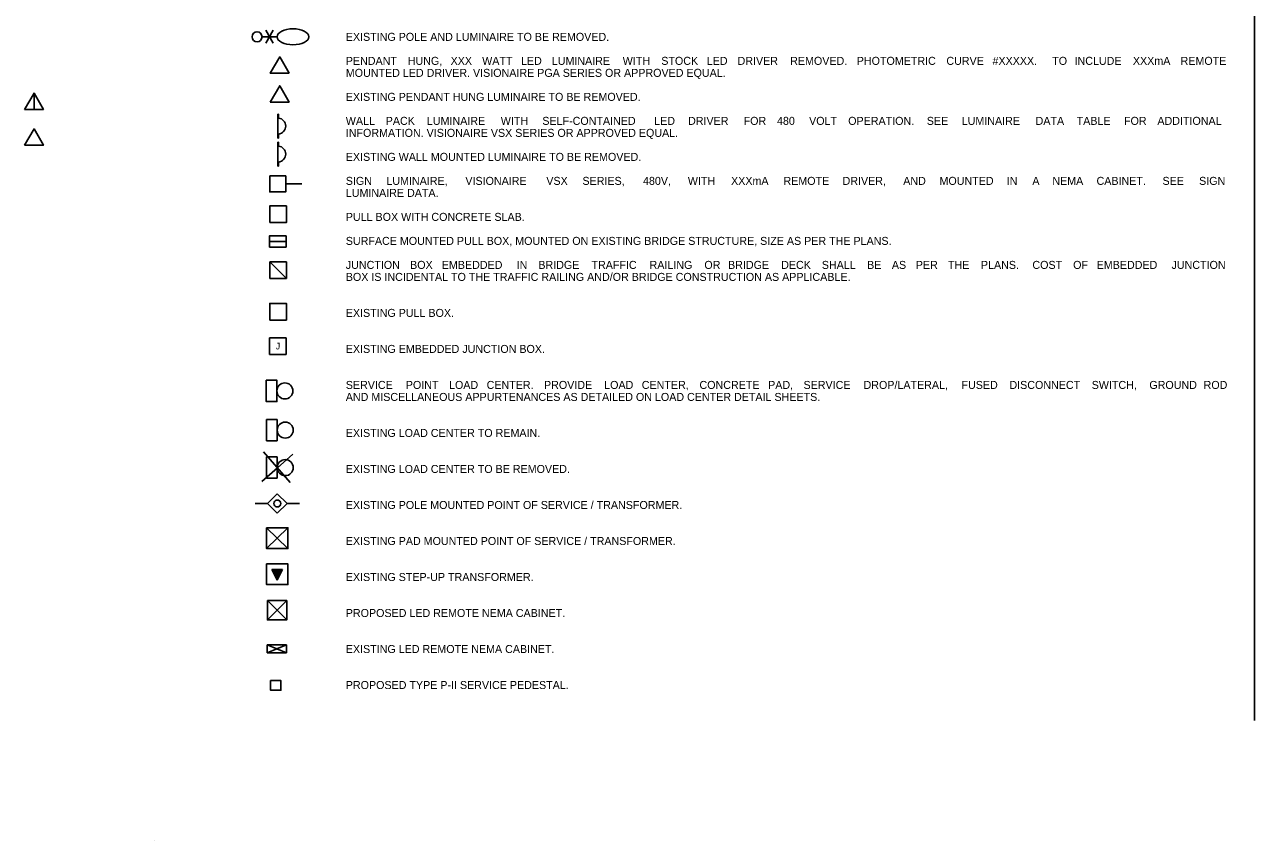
# Model space of a CAD drawing. Extents: x -1500 to -654, y -278 to 331.
# Drawn here: x -1500.3 to -1039.2, y -278.3 to 27.5 of the extents above; entities that cross this region are included whole.
import ezdxf

# ---------------------------------------------------------------- set-up
doc = ezdxf.new("R2010")
doc.units = 0
for name, color, linetype in [('AdhocPoint_dp', 7, 'Continuous'), ('ControllerP', 7, 'Continuous'), ('Default', 7, 'Continuous'), ('ElecMisc_ep', 7, 'Continuous'), ('JunctBoxA', 7, 'Continuous'), ('LoadCenter', 7, 'Continuous'), ('Logo_dp', 7, 'Continuous'), ('Miscellaneous3', 7, 'Continuous'), ('SheetBorder_dp', 7, 'Continuous'), ('SheetLines_dp', 7, 'Continuous'), ('SignPanel', 7, 'Continuous')]:
    doc.layers.add(name, color=color, linetype=linetype)

# ---------------------------------------------------------------- blocks, each defined once
blk = doc.blocks.new('EPoleLumRmv')
at = {"layer": 'Logo_dp'}
for p, q in [((-0.00352, -0.0088), (0.00352, -0.00474)), ((0.00352, -0.0088), (-0.00352, -0.00474)), ((0, -0.00271), (0, -0.01083))]:
    blk.add_line(p, q, dxfattribs=at)
blk.add_circle((0, 0), 0.00271, dxfattribs=at)
blk.add_ellipse((0, -0.01949), major_axis=(0, -0.00866), ratio=0.5, dxfattribs=at)

msp = doc.modelspace()

# ---------------------------------------------------------------- linework, layer by layer
at = {"layer": 'AdhocPoint_dp'}
for p, q in [((-1405.09, -6.02), (-1405.39, -6.02)), ((-1405.39, -6.02), (-1405.39, -15.02)), ((-1405.09, -7.54), (-1405.09, -6.02)), ((-1405.09, -15.02), (-1405.09, -13.51)), ((-1405.39, -15.02), (-1405.09, -15.02)), ((-1405.39, -25.52), (-1405.39, -16.52)), ((-1405.39, -16.52), (-1405.09, -16.52)), ((-1405.09, -16.52), (-1405.09, -18.04)), ((-1405.09, -25.52), (-1405.39, -25.52)), ((-1405.09, -24.01), (-1405.09, -25.52))]:
    msp.add_line(p, q, dxfattribs=at)
for points in [[(-1401.1, 9.31), (-1408.17, 9.31), (-1404.64, 15.43)], [(-1500.3, -4.28), (-1493.23, -4.28), (-1496.76, 1.84)], [(-1496.76, 1.84), (-1493.23, -4.28), (-1496.76, -4.28)], [(-1408.17, -1.53), (-1401.1, -1.53), (-1404.64, 4.59)], [(-1500.3, -17.69), (-1493.23, -17.69), (-1496.76, -11.57)]]:
    msp.add_lwpolyline(points, close=True, dxfattribs=at)
for centre in [(-1405.39, -10.52), (-1405.39, -21.02)]:
    msp.add_arc(centre, 3, 275.7392, 84.2608, dxfattribs=at)
at = {"layer": 'ControllerP'}
for p, q in [((-1409.27, -188.4), (-1401.98, -195.64)), ((-1409.27, -195.64), (-1401.98, -188.4)), ((-1409.3, -205.02), (-1402.08, -208.03)), ((-1402.08, -205.02), (-1409.3, -208.03)), ((-1409.3, -205.02), (-1402.08, -205.02)), ((-1409.3, -208.03), (-1409.3, -205.02)), ((-1402.08, -205.02), (-1402.08, -208.03)), ((-1402.08, -208.03), (-1409.3, -208.03))]:
    msp.add_line(p, q, dxfattribs=at)
for points in [[(-1409.27, -188.4), (-1401.98, -188.4), (-1401.98, -195.64), (-1409.27, -195.64)], [(-1408.08, -218.44), (-1404.18, -218.44), (-1404.18, -222.02), (-1408.08, -222.02)]]:
    msp.add_lwpolyline(points, close=True, dxfattribs=at)
at = {"layer": 'Default'}
msp.add_circle((-1405.56, -152.03), 1.3, dxfattribs=at)
at = {"layer": 'ElecMisc_ep'}
for p, q in [((-1409.57, -168.9), (-1401.56, -161.14)), ((-1409.57, -161.14), (-1401.56, -168.91)), ((-1405.56, -180.82), (-1407.56, -176.82)), ((-1407.56, -176.82), (-1403.56, -176.82)), ((-1407.36, -176.82), (-1405.56, -180.82)), ((-1405.56, -180.82), (-1407.16, -176.82)), ((-1405.56, -180.82), (-1406.96, -176.82)), ((-1405.56, -180.82), (-1406.76, -176.82)), ((-1405.56, -180.82), (-1406.56, -176.82)), ((-1405.56, -180.82), (-1406.36, -176.82)), ((-1405.56, -180.82), (-1406.16, -176.82)), ((-1405.56, -180.82), (-1405.96, -176.82)), ((-1405.56, -180.82), (-1405.76, -176.82)), ((-1405.56, -180.82), (-1405.36, -176.82)), ((-1405.56, -180.82), (-1405.16, -176.82)), ((-1405.56, -180.82), (-1404.96, -176.82)), ((-1405.56, -180.82), (-1404.76, -176.82)), ((-1405.56, -180.82), (-1404.36, -176.82)), ((-1405.56, -180.82), (-1404.16, -176.82)), ((-1405.56, -180.82), (-1403.96, -176.82)), ((-1405.56, -180.82), (-1403.77, -176.82)), ((-1403.56, -176.82), (-1405.56, -180.82)), ((-1405.56, -180.82), (-1405.56, -176.82)), ((-1405.56, -180.82), (-1404.56, -176.82))]:
    msp.add_line(p, q, dxfattribs=at)
for points in [[(-1409.57, -161.14), (-1401.56, -161.14), (-1401.56, -168.91), (-1409.57, -168.9)], [(-1409.57, -174.64), (-1401.56, -174.64), (-1401.56, -182.41), (-1409.57, -182.4)]]:
    msp.add_lwpolyline(points, close=True, dxfattribs=at)
at = {"layer": 'JunctBoxA'}
for p, q in [((-1408.51, -55.88), (-1408.51, -51.71)), ((-1408.51, -51.71), (-1402.26, -51.71)), ((-1402.26, -53.8), (-1408.51, -53.8)), ((-1402.26, -51.71), (-1402.26, -55.88)), ((-1402.26, -55.88), (-1408.51, -55.88))]:
    msp.add_line(p, q, dxfattribs=at)
msp.add_lwpolyline([(-1402.26, -53.8), (-1408.51, -53.8), (-1408.51, -51.71), (-1402.26, -51.71)], close=True, dxfattribs=at)
at = {"layer": 'LoadCenter'}
for p, q in [((-1402.39, -32.21), (-1396.39, -32.21)), ((-1409.7, -105.83), (-1405.7, -105.83)), ((-1409.7, -113.83), (-1409.7, -105.83)), ((-1405.7, -105.83), (-1405.7, -113.83)), ((-1405.7, -113.83), (-1409.7, -113.83)), ((-1409.56, -120.49), (-1405.56, -120.49)), ((-1409.56, -128.49), (-1409.56, -120.49)), ((-1405.56, -120.49), (-1405.56, -128.49)), ((-1405.56, -128.49), (-1409.56, -128.49)), ((-1410.7, -132.71), (-1400.68, -144.11)), ((-1405.51, -138.62), (-1399.69, -133.5)), ((-1409.56, -134.58), (-1405.56, -134.58)), ((-1409.56, -142.58), (-1409.56, -134.58)), ((-1405.56, -134.58), (-1405.56, -142.58)), ((-1411.32, -143.73), (-1405.51, -138.62)), ((-1405.56, -142.58), (-1409.56, -142.58)), ((-1409.24, -152.03), (-1413.88, -152.03)), ((-1409.24, -152.03), (-1405.56, -148.35)), ((-1405.56, -155.7), (-1409.24, -152.03)), ((-1405.56, -148.35), (-1401.89, -152.03)), ((-1401.89, -152.03), (-1405.56, -155.7)), ((-1397.24, -152.03), (-1401.89, -152.03))]:
    msp.add_line(p, q, dxfattribs=at)
for points in [[(-1408.39, -29.21), (-1402.39, -29.21), (-1402.39, -35.21), (-1408.39, -35.21)], [(-1409.7, -105.83), (-1405.7, -105.83), (-1405.7, -113.83), (-1409.7, -113.83)]]:
    msp.add_lwpolyline(points, close=True, dxfattribs=at)
for centre in [(-1402.7, -109.83), (-1402.7, -109.83), (-1402.56, -124.49), (-1402.56, -138.58)]:
    msp.add_circle(centre, 3, dxfattribs=at)
at = {"layer": 'Miscellaneous3'}
msp.add_line((-1039.17, 240.54), (-1039.17, -233.32), dxfattribs=at)
at = {"layer": 'SheetLines_dp'}
for p, q in [((-1408.35, -61.38), (-1402.1, -61.38)), ((-1408.35, -67.63), (-1408.35, -61.38)), ((-1408.35, -61.38), (-1402.1, -67.63)), ((-1402.1, -61.38), (-1402.1, -67.63)), ((-1402.1, -67.63), (-1408.35, -67.63)), ((-1408.42, -89.9), (-1402.17, -89.9)), ((-1408.42, -96.15), (-1408.42, -89.9)), ((-1402.17, -89.9), (-1402.17, -96.15)), ((-1402.17, -96.15), (-1408.42, -96.15))]:
    msp.add_line(p, q, dxfattribs=at)
for points in [[(-1408.39, -46.7), (-1402.14, -46.7), (-1402.14, -40.45), (-1408.39, -40.45)], [(-1408.35, -83.25), (-1402.1, -83.25), (-1402.1, -77), (-1408.35, -77)]]:
    msp.add_lwpolyline(points, close=True, dxfattribs=at)
at = {"layer": 'SignPanel'}
msp.add_line((-1451.67, -278.32), (-1451.67, -278.32), dxfattribs=at)

# ---------------------------------------------------------------- block references
at = {"layer": 'Logo_dp', "xscale": 690.9505022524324, "yscale": 690.9505022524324, "rotation": 89.99999999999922}
msp.add_blockref('EPoleLumRmv', (-1413.13, 22.94), dxfattribs=at)

# ---------------------------------------------------------------- texts
at = {"layer": 'SheetBorder_dp'}
for s, p in [('EXISTING POLE AND LUMINAIRE TO BE REMOVED.', (-1379.86, 21.43)), ('PENDANT ', (-1379.86, 12.43)), ('HUNG, ', (-1356.63, 12.43)), ('XXX ', (-1340.56, 12.43)), ('WATT ', (-1328.72, 12.43)), ('LED ', (-1314.18, 12.43)), ('LUMINAIRE ', (-1302.62, 12.43)), ('WITH ', (-1276.03, 12.43)), ('STOCK ', (-1261.57, 12.43)), ('LED ', (-1244.52, 12.43)), ('DRIVER ', (-1232.96, 12.43)), ('REMOVED. ', (-1213.24, 12.43)), ('PHOTOMETRIC ', (-1188.27, 12.43)), ('CURVE ', (-1154.66, 12.43)), ('#XXXXX. ', (-1137.37, 12.43)), ('TO ', (-1114.98, 12.43)), ('INCLUDE ', (-1106.61, 12.43)), ('XXXmA ', (-1084.73, 12.43)), ('REMOTE ', (-1066.85, 12.43)), ('MOUNTED LED DRIVER. VISIONAIRE PGA SERIES OR APPROVED EQUAL.', (-1379.86, 7.93)), ('EXISTING PENDANT HUNG LUMINAIRE TO BE REMOVED.', (-1379.86, -1.07)), ('WALL ', (-1379.86, -10.07)), ('PACK ', (-1364.89, -10.07)), ('LUMINAIRE ', (-1349.45, -10.07)), ('WITH ', (-1321.75, -10.07)), ('SELF-CONTAINED ', (-1306.17, -10.07)), ('LED ', (-1264.21, -10.07)), ('DRIVER ', (-1251.53, -10.07)), ('FOR ', (-1230.69, -10.07)), ('480 ', (-1218.18, -10.07)), ('VOLT ', (-1206.14, -10.07)), ('OPERATION. ', (-1191.48, -10.07)), ('SEE ', (-1162.01, -10.07)), ('LUMINAIRE ', (-1148.92, -10.07)), ('DATA ', (-1121.21, -10.07)), ('TABLE ', (-1105.82, -10.07)), ('FOR ', (-1088.06, -10.07)), ('ADDITIONAL ', (-1075.55, -10.07)), ('INFORMATION. VISIONAIRE VSX SERIES OR APPROVED EQUAL.', (-1379.86, -14.57)), ('EXISTING WALL MOUNTED LUMINAIRE TO BE REMOVED.', (-1379.86, -23.57)), ('SIGN ', (-1379.86, -32.57)), ('LUMINAIRE, ', (-1364.64, -32.57)), ('VISIONAIRE ', (-1335.02, -32.57)), ('VSX ', (-1304.67, -32.57)), ('SERIES, ', (-1291.12, -32.57)), ('480V, ', (-1268.42, -32.57)), ('WITH ', (-1251.61, -32.57)), ('XXXmA ', (-1235.4, -32.57)), ('REMOTE ', (-1215.76, -32.57)), ('DRIVER, ', (-1193.59, -32.57)), ('AND ', (-1170.84, -32.57)), ('MOUNTED ', (-1157.25, -32.57)), ('IN ', (-1132.03, -32.57)), ('A ', (-1122.43, -32.57)), ('NEMA ', (-1114.94, -32.57)), ('CABINET. ', (-1098.36, -32.57)), ('SEE ', (-1073.62, -32.57)), ('SIGN ', (-1059.9, -32.57)), ('LUMINAIRE DATA.', (-1379.86, -37.07)), ('PULL BOX WITH CONCRETE SLAB. ', (-1379.86, -46.07)), ('SURFACE MOUNTED PULL BOX, MOUNTED ON EXISTING BRIDGE STRUCTURE, SIZE AS PER THE PLANS.', (-1379.86, -55.07)), ('JUNCTION ', (-1379.86, -64.07)), ('BOX ', (-1355.75, -64.07)), ('EMBEDDED ', (-1343.87, -64.07)), ('IN ', (-1315.79, -64.07)), ('BRIDGE ', (-1307.66, -64.07)), ('TRAFFIC ', (-1287.74, -64.07)), ('RAILING ', (-1265.96, -64.07)), ('OR ', (-1245.41, -64.07)), ('BRIDGE ', (-1236.53, -64.07)), ('DECK ', (-1216.62, -64.07)), ('SHALL ', (-1201.37, -64.07)), ('BE ', (-1184.39, -64.07)), ('AS ', (-1175.11, -64.07)), ('PER ', (-1166.14, -64.07)), ('THE ', (-1154.08, -64.07)), ('PLANS. ', (-1141.72, -64.07)), (' COST ', (-1123.52, -64.07)), ('OF ', (-1107.13, -64.07)), ('EMBEDDED ', (-1098.32, -64.07)), ('JUNCTION ', (-1070.25, -64.07)), ('BOX IS INCIDENTAL TO THE TRAFFIC RAILING AND/OR BRIDGE CONSTRUCTION AS APPLICABLE. ', (-1379.86, -68.57)), ('EXISTING PULL BOX.', (-1379.86, -82.07)), ('EXISTING EMBEDDED JUNCTION BOX.', (-1379.86, -95.57)), ('SERVICE ', (-1379.86, -109.07)), ('POINT ', (-1357.36, -109.07)), ('LOAD ', (-1341.15, -109.07)), ('CENTER. ', (-1327.05, -109.07)), ('PROVIDE ', (-1305.54, -109.07)), ('LOAD ', (-1282.98, -109.07)), ('CENTER, ', (-1268.88, -109.07)), ('CONCRETE ', (-1247.25, -109.07)), ('SERVICE ', (-1208.23, -109.07)), ('DROP/LATERAL, ', (-1185.73, -109.07)), ('FUSED ', (-1149, -109.07)), ('DISCONNECT ', (-1131.02, -109.07)), ('SWITCH, ', (-1100.18, -109.07)), ('GROUND ', (-1078.56, -109.07)), ('ROD ', (-1058.22, -109.07)), ('AND MISCELLANEOUS APPURTENANCES AS DETAILED ON LOAD CENTER DETAIL SHEETS.  ', (-1379.86, -113.57)), ('PAD, ', (-1221.5, -109.07)), ('EXISTING LOAD CENTER TO REMAIN.', (-1379.86, -127.07)), ('EXISTING LOAD CENTER TO BE REMOVED.', (-1379.86, -140.57)), ('EXISTING POLE MOUNTED POINT OF SERVICE / TRANSFORMER.', (-1379.86, -154.07)), ('EXISTING PAD MOUNTED POINT OF SERVICE / TRANSFORMER.', (-1379.86, -167.57)), ('EXISTING STEP-UP TRANSFORMER.', (-1379.86, -181.07)), ('PROPOSED LED REMOTE NEMA CABINET.', (-1379.86, -194.57)), ('EXISTING LED REMOTE NEMA CABINET.', (-1379.86, -208.07)), ('PROPOSED TYPE P-II SERVICE PEDESTAL.', (-1379.86, -221.57))]:
    msp.add_text(s, height=3, dxfattribs=at).set_placement(p)
at = {"layer": 'SheetLines_dp'}
msp.add_text('J', height=2.5, dxfattribs=at).set_placement((-1406.14, -94.27))

doc.saveas('drawing.dxf')
